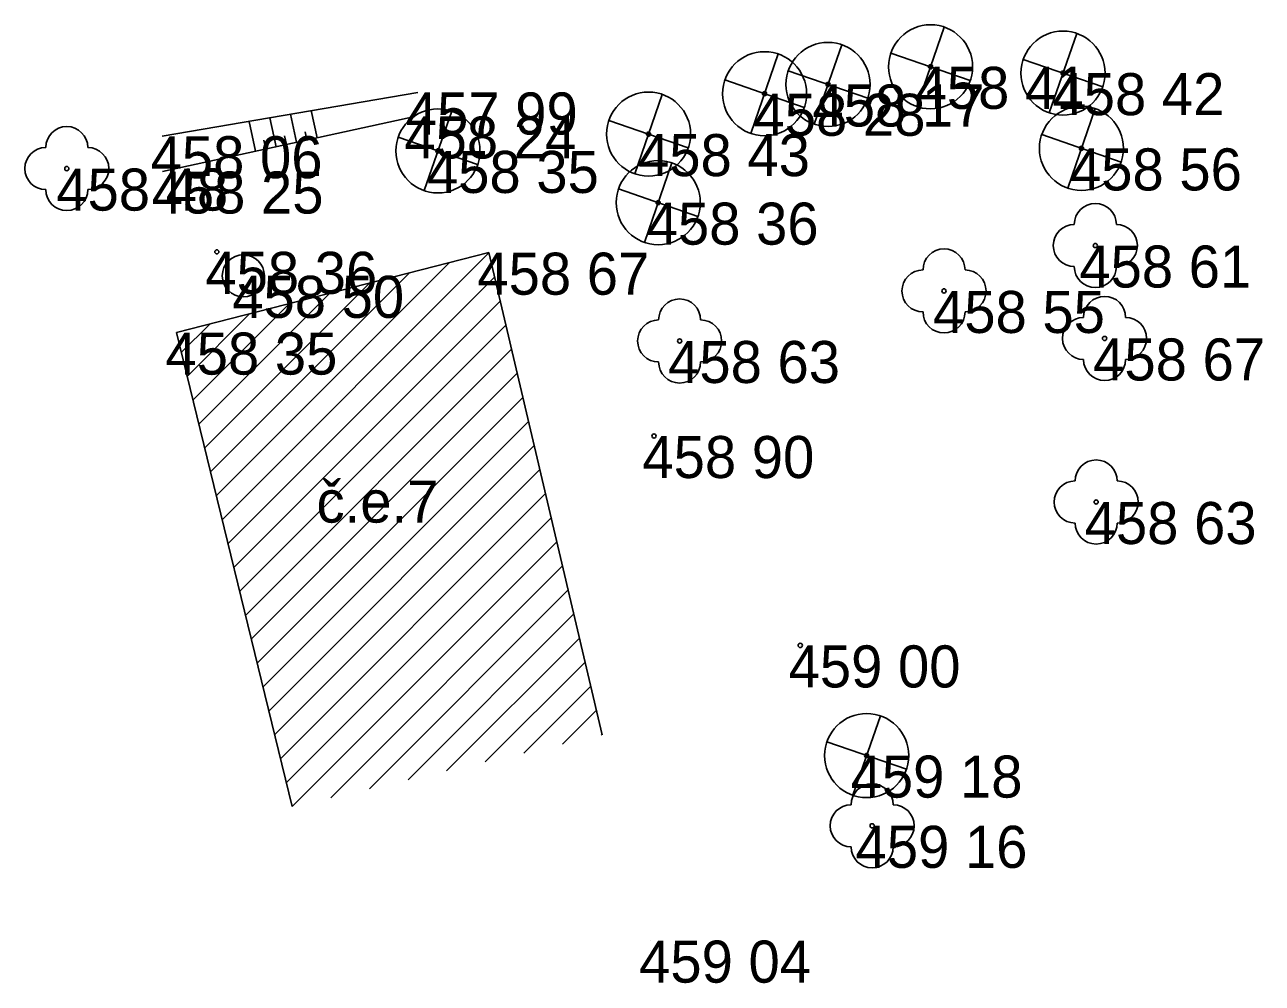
# Model space of a CAD drawing. Extents: x -554123 to -553118, y -1076825 to -1073672.
# Drawn here: x -553704.91 to -553675.47, y -1075304.81 to -1075282.02 of the extents above; entities that cross this region are included whole.
import ezdxf

# ---------------------------------------------------------------- set-up
doc = ezdxf.new("R2010")
doc.units = 0
for name, color, linetype in [('1', 7, 'Continuous'), ('14', 7, 'Continuous'), ('26', 7, 'Continuous'), ('27', 7, 'Continuous'), ('32', 7, 'Continuous'), ('34', 7, 'Continuous'), ('40', 7, 'Continuous'), ('54', 7, 'Continuous'), ('6', 7, 'Continuous')]:
    doc.layers.add(name, color=color, linetype=linetype)

# ---------------------------------------------------------------- blocks, each defined once
blk = doc.blocks.new('POINT_DISPLAY')
blk.add_line((0, 0), (0, 0))
blk = doc.blocks.new('SAK')
at = {"layer": '40'}
blk.add_circle((0, 0), 0.5, dxfattribs=at)
blk = doc.blocks.new('T')
at = {"layer": '6'}
blk.add_circle((0, 0), 0.05, dxfattribs=at)
blk = doc.blocks.new('STL')
at = {"layer": '34'}
blk.add_circle((0, 0), 0.05, dxfattribs=at)
for centre, start, end in [((0, 0.5), 0, 180), ((-0.5, 0), 90, 270), ((0.5, 0), 270, 90), ((0, -0.5), 180, 0)]:
    blk.add_arc(centre, 0.5, start, end, dxfattribs=at)
blk = doc.blocks.new('STJ')
at = {"layer": '34'}
for p, q in [((-0.327, -0.945), (0.327, 0.945)), ((0.945, -0.327), (-0.945, 0.327))]:
    blk.add_line(p, q, dxfattribs=at)
for radius in [1, 0.0496]:
    blk.add_circle((0, 0), radius, dxfattribs=at)

msp = doc.modelspace()

# ---------------------------------------------------------------- linework, layer by layer
at = {"layer": '14'}
for p, q in [((-553693.87, -1075287.44), (-553701.3, -1075289.34)), ((-553691.171, -1075298.909), (-553693.87, -1075287.44)), ((-553701.3, -1075289.34), (-553698.551, -1075300.614))]:
    msp.add_line(p, q, dxfattribs=at)
at = {"layer": '26'}
for p, q in [((-553699.419, -1075285.027), (-553699.574, -1075284.317)), ((-553698.93, -1075284.921), (-553699.08, -1075284.232)), ((-553698.442, -1075284.814), (-553698.587, -1075284.148)), ((-553697.953, -1075284.707), (-553698.094, -1075284.063)), ((-553698.198, -1075284.761), (-553698.241, -1075284.564)), ((-553699.175, -1075284.974), (-553699.221, -1075284.764)), ((-553698.686, -1075284.867), (-553698.731, -1075284.664))]:
    msp.add_line(p, q, dxfattribs=at)
at = {"layer": '27'}
for p, q in [((-553701.64, -1075284.67), (-553695.56, -1075283.63)), ((-553701.63, -1075285.51), (-553695.63, -1075284.2))]:
    msp.add_line(p, q, dxfattribs=at)
at = {"layer": '32'}
for p, q in [((-553700.214, -1075293.792), (-553693.869, -1075287.446)), ((-553700.353, -1075293.224), (-553694.81, -1075287.68)), ((-553700.63, -1075292.087), (-553696.71, -1075288.166)), ((-553700.492, -1075292.655), (-553695.76, -1075287.923)), ((-553700.076, -1075294.361), (-553693.734, -1075288.019)), ((-553700.769, -1075291.518), (-553697.66, -1075288.409)), ((-553700.908, -1075290.95), (-553698.61, -1075288.652)), ((-553699.937, -1075294.929), (-553693.599, -1075288.591)), ((-553701.046, -1075290.381), (-553699.56, -1075288.895)), ((-553701.185, -1075289.813), (-553700.51, -1075289.138)), ((-553699.799, -1075295.498), (-553693.464, -1075289.163)), ((-553699.66, -1075296.066), (-553693.33, -1075289.736)), ((-553699.521, -1075296.635), (-553693.195, -1075290.308)), ((-553699.383, -1075297.203), (-553693.06, -1075290.881)), ((-553699.244, -1075297.772), (-553692.926, -1075291.453)), ((-553699.105, -1075298.34), (-553692.791, -1075292.025)), ((-553698.967, -1075298.909), (-553692.656, -1075292.598)), ((-553698.828, -1075299.477), (-553692.521, -1075293.17)), ((-553698.69, -1075300.046), (-553692.387, -1075293.743)), ((-553698.551, -1075300.614), (-553692.252, -1075294.315)), ((-553697.631, -1075300.402), (-553692.117, -1075294.887)), ((-553696.712, -1075300.189), (-553691.983, -1075295.46)), ((-553695.792, -1075299.977), (-553691.848, -1075296.032)), ((-553694.873, -1075299.764), (-553691.713, -1075296.605)), ((-553693.953, -1075299.552), (-553691.579, -1075297.177)), ((-553693.034, -1075299.339), (-553691.444, -1075297.75)), ((-553692.114, -1075299.127), (-553691.309, -1075298.322)), ((-553691.195, -1075298.914), (-553691.174, -1075298.894))]:
    msp.add_line(p, q, dxfattribs=at)

# ---------------------------------------------------------------- block references
at = {"layer": '1'}
for p in [(-553683.36, -1075283.02), (-553680.21, -1075283.17), (-553685.8, -1075283.44), (-553695.56, -1075283.63), (-553687.31, -1075283.66), (-553695.63, -1075284.2), (-553690.07, -1075284.62), (-553701.64, -1075284.67), (-553695.08, -1075285.02), (-553679.77, -1075284.96), (-553703.91, -1075285.44), (-553701.63, -1075285.51), (-553689.84, -1075286.25), (-553679.44, -1075287.27), (-553700.34, -1075287.42), (-553693.87, -1075287.44), (-553699.71, -1075287.99), (-553683.04, -1075288.35), (-553701.3, -1075289.34), (-553689.33, -1075289.54), (-553679.22, -1075289.48), (-553689.94, -1075291.8), (-553679.42, -1075293.37), (-553686.46, -1075296.78), (-553684.88, -1075299.4), (-553684.75, -1075301.07), (-553690.03, -1075303.8)]:
    msp.add_blockref('POINT_DISPLAY', p, dxfattribs=at)
at = {"layer": '32'}
msp.add_blockref('POINT_DISPLAY', (-553698.551, -1075300.614), dxfattribs=at)
at = {"layer": '34'}
for name, p in [('STJ', (-553683.36, -1075283.02)), ('STJ', (-553680.21, -1075283.17)), ('STJ', (-553685.8, -1075283.44)), ('STJ', (-553687.31, -1075283.66)), ('STJ', (-553690.07, -1075284.62)), ('STJ', (-553695.08, -1075285.02)), ('STJ', (-553679.77, -1075284.96)), ('STL', (-553703.91, -1075285.44)), ('STJ', (-553689.84, -1075286.25)), ('STL', (-553679.44, -1075287.27)), ('STL', (-553683.04, -1075288.35)), ('STL', (-553689.33, -1075289.54)), ('STL', (-553679.22, -1075289.48)), ('STL', (-553679.42, -1075293.37)), ('STJ', (-553684.88, -1075299.4)), ('STL', (-553684.75, -1075301.07))]:
    msp.add_blockref(name, p, dxfattribs=at)
at = {"layer": '40'}
msp.add_blockref('SAK', (-553699.71, -1075287.99), dxfattribs=at)
at = {"layer": '6'}
for p in [(-553700.34, -1075287.42), (-553689.94, -1075291.8), (-553686.46, -1075296.78)]:
    msp.add_blockref('T', p, dxfattribs=at)

# ---------------------------------------------------------------- texts
at = {"layer": '54'}
msp.add_text('č.e.7', height=1, dxfattribs=at).set_placement((-553697.968, -1075293.86))
at = {"layer": '6'}
for s, p in [('458 41 ', (-553683.717, -1075284.02)), ('458 42 ', (-553680.46, -1075284.17)), ('458 17 ', (-553686.169, -1075284.44)), ('457 99 ', (-553695.844, -1075284.63)), ('458 28 ', (-553687.572, -1075284.66)), ('458 24 ', (-553695.88, -1075285.2)), ('458 43 ', (-553690.32, -1075285.62)), ('458 06 ', (-553701.916, -1075285.67)), ('458 56 ', (-553680.044, -1075285.96)), ('458 35 ', (-553695.342, -1075286.02)), ('458 48 ', (-553704.16, -1075286.44)), ('458 25 ', (-553701.892, -1075286.51)), ('458 36 ', (-553690.114, -1075287.25)), ('458 61 ', (-553679.821, -1075288.27)), ('458 36 ', (-553700.614, -1075288.42)), ('458 67 ', (-553694.142, -1075288.44)), ('458 50 ', (-553699.974, -1075288.99)), ('458 55 ', (-553683.302, -1075289.35)), ('458 35 ', (-553701.562, -1075290.34)), ('458 63 ', (-553689.604, -1075290.54)), ('458 67 ', (-553679.492, -1075290.48)), ('458 90 ', (-553690.216, -1075292.8)), ('458 63 ', (-553679.694, -1075294.37)), ('459 00 ', (-553686.738, -1075297.78)), ('459 18 ', (-553685.263, -1075300.4)), ('459 16 ', (-553685.145, -1075302.07)), ('459 04 ', (-553690.294, -1075304.8))]:
    msp.add_text(s, height=1, dxfattribs=at).set_placement(p)

doc.saveas('drawing.dxf')
